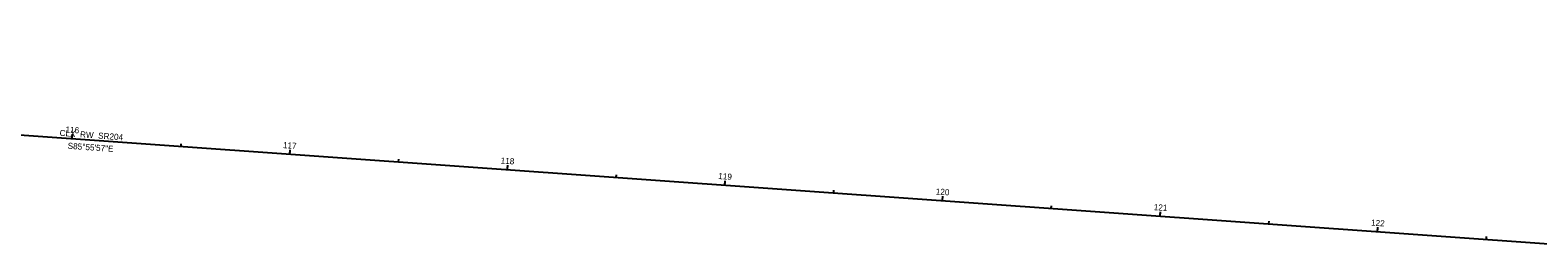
# Model space of a CAD drawing. Extents: x 1898401 to 1901169, y 703131 to 703379.
# Drawn here: x 1899080 to 1899771, y 703230 to 703330 of the extents above; entities that cross this region are included whole.
import ezdxf

# ---------------------------------------------------------------- set-up
doc = ezdxf.new("R2010")
doc.units = 0
for name, color, linetype in [('RW_X_CL', 7, 'Continuous'), ('RW_X_CL_1000_Bearings', 7, 'Continuous'), ('RW_X_CL_1000_Distances', 7, 'Continuous'), ('RW_X_CL_1000_Stations', 7, 'Continuous'), ('RW_X_CL_100_Bearings', 7, 'Continuous'), ('RW_X_CL_100_Distances', 7, 'Continuous'), ('RW_X_CL_100_Stations', 7, 'Continuous'), ('RW_X_CL_500_Bearings', 7, 'Continuous'), ('RW_X_CL_500_Distances', 7, 'Continuous'), ('RW_X_CL_500_Stations', 7, 'Continuous')]:
    doc.layers.add(name, color=color, linetype=linetype)

msp = doc.modelspace()

# ---------------------------------------------------------------- linework, layer by layer
at = {"layer": 'RW_X_CL'}
msp.add_line((1898401.58, 703330.4), (1899815.76, 703229.84), dxfattribs=at)
at = {"layer": 'RW_X_CL_1000_Stations'}
msp.add_line((1899498.46, 703252.4), (1899498.6, 703254.4), dxfattribs=at)
at = {"layer": 'RW_X_CL_100_Stations'}
for p, q in [((1899099.47, 703280.78), (1899099.61, 703282.77)), ((1899149.34, 703277.23), (1899149.43, 703278.43)), ((1899199.22, 703273.68), (1899199.36, 703275.68)), ((1899249.09, 703270.14), (1899249.18, 703271.33)), ((1899298.97, 703266.59), (1899299.11, 703268.58)), ((1899348.84, 703263.04), (1899348.93, 703264.24)), ((1899398.71, 703259.5), (1899398.86, 703261.49)), ((1899448.59, 703255.95), (1899448.67, 703257.15)), ((1899498.46, 703252.4), (1899498.6, 703254.4)), ((1899548.34, 703248.86), (1899548.42, 703250.05)), ((1899598.21, 703245.31), (1899598.35, 703247.3)), ((1899648.08, 703241.76), (1899648.17, 703242.96)), ((1899697.96, 703238.22), (1899698.1, 703240.21)), ((1899747.83, 703234.67), (1899747.92, 703235.87))]:
    msp.add_line(p, q, dxfattribs=at)
at = {"layer": 'RW_X_CL_500_Stations'}
for p, q in [((1899099.47, 703280.78), (1899099.55, 703281.97)), ((1899199.22, 703273.68), (1899199.3, 703274.88)), ((1899298.97, 703266.59), (1899299.05, 703267.79)), ((1899398.71, 703259.5), (1899398.8, 703260.69)), ((1899498.46, 703252.4), (1899498.6, 703254.4)), ((1899598.21, 703245.31), (1899598.3, 703246.51)), ((1899697.96, 703238.22), (1899698.04, 703239.41))]:
    msp.add_line(p, q, dxfattribs=at)

# ---------------------------------------------------------------- texts
at = {"layer": 'RW_X_CL_1000_Bearings'}
msp.add_text('S85°55\'57"E', height=2.8, rotation=355.93252, dxfattribs=at).set_placement((1899097.29, 703276.12))
at = {"layer": 'RW_X_CL_1000_Distances'}
msp.add_text('CLX_RW_SR204', height=2.8, rotation=355.93252, dxfattribs=at).set_placement((1899093.61, 703282.02))
at = {"layer": 'RW_X_CL_1000_Stations'}
msp.add_text('120', height=2.8, rotation=355.93252, dxfattribs=at).set_placement((1899495.3, 703255.18))
at = {"layer": 'RW_X_CL_100_Bearings'}
msp.add_text('S85°55\'57"E', height=2.8, rotation=355.93252, dxfattribs=at).set_placement((1899097.29, 703276.12))
at = {"layer": 'RW_X_CL_100_Distances'}
msp.add_text('CLX_RW_SR204', height=2.8, rotation=355.93252, dxfattribs=at).set_placement((1899093.61, 703282.02))
at = {"layer": 'RW_X_CL_100_Stations'}
for s, p in [('116', (1899096.3, 703283.55)), ('117', (1899195.99, 703276.43)), ('118', (1899295.82, 703269.36)), ('119', (1899395.58, 703262.27)), ('120', (1899495.3, 703255.18)), ('121', (1899595.24, 703248.03)), ('122', (1899694.86, 703240.94))]:
    msp.add_text(s, height=2.8, rotation=355.93252, dxfattribs=at).set_placement(p)
at = {"layer": 'RW_X_CL_500_Bearings'}
msp.add_text('S85°55\'57"E', height=2.8, rotation=355.93252, dxfattribs=at).set_placement((1899097.29, 703276.12))
at = {"layer": 'RW_X_CL_500_Distances'}
msp.add_text('CLX_RW_SR204', height=2.8, rotation=355.93252, dxfattribs=at).set_placement((1899093.61, 703282.02))
at = {"layer": 'RW_X_CL_500_Stations'}
msp.add_text('120', height=2.8, rotation=355.93252, dxfattribs=at).set_placement((1899495.3, 703255.18))

doc.saveas('drawing.dxf')
